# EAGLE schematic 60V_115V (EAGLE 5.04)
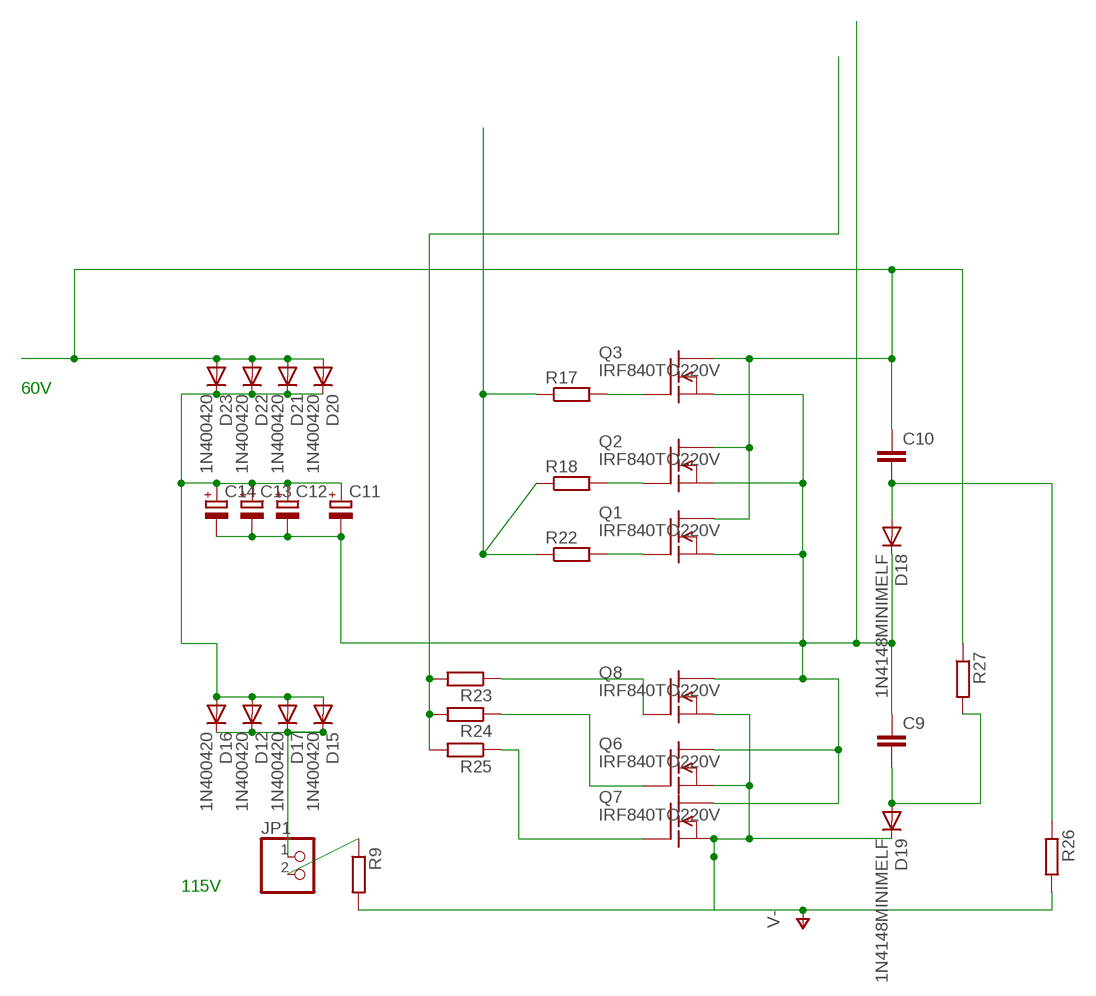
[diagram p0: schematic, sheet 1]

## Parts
C9  C-EUC1812  [C1812]
C10  C-EUC1812K  [C1812K]
C11  CPOL-EUSANYO_SMD_E7  [SANYO-OSCON_SMD_E7]
C12  CPOL-EUSANYO_SMD_E7  [SANYO-OSCON_SMD_E7]
C13  CPOL-EUSANYO_SMD_E7  [SANYO-OSCON_SMD_E7]
C14  CPOL-EUSANYO_SMD_E7  [SANYO-OSCON_SMD_E7]
D12  1N400420  [DO41-20]
D15  1N400420  [DO41-20]
D16  1N400420  [DO41-20]
D17  1N400420  [DO41-20]
D18  1N4148MINIMELF  [MINIMELF]
D19  1N4148MINIMELF  [MINIMELF]
D20  1N400420  [DO41-20]
D21  1N400420  [DO41-20]
D22  1N400420  [DO41-20]
D23  1N400420  [DO41-20]
JP1  PINHD-1X2  [1X02]
Q1  IRF840TO220V  [TO220V]
Q2  IRF840TO220V  [TO220V]
Q3  IRF840TO220V  [TO220V]
Q6  IRF840TO220V  [TO220V]
Q7  IRF840TO220V  [TO220V]
Q8  IRF840TO220V  [TO220V]
R9  R-EU_0207/10  [0207/10]
R17  R-EU_R1206  [R1206]
R18  R-EU_R1206  [R1206]
R22  R-EU_R1206  [R1206]
R23  R-EU_R1206  [R1206]
R24  R-EU_R1206  [R1206]
R25  R-EU_R1206  [R1206]
R26  R-EU_0207/25  [0207/25]
R27  R-EU_0207/30  [0207/30]

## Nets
DRAIN: C9.1 C11.- C12.- C13.- C14.- D18.C Q1.3(S) Q2.3(S) Q3.3(S) Q6.2(D) Q7.2(D) Q8.2(D)
GATE: R17.1 R18.1 R22.1
N$1: JP1.2 R9.1
N$2: C11.+ C12.+ C13.+ C14.+ D12.A D15.A D16.A D17.A D20.C D21.C D22.C D23.C
N$4: Q2.1(G) R18.2
N$9: R23.2 R24.2 R25.2
N$11: Q3.1(G) R17.2
N$23: Q1.1(G) R22.2
N$24: C10.2 D18.A R26.1
N$25: Q7.1(G) R25.1
N$26: Q6.1(G) R24.1
N$27: Q8.1(G) R23.1
N$28: C9.2 D19.A R27.2
OUT+: D12.C D15.C D16.C D17.C JP1.1
V-: D19.C Q6.3(S) Q7.3(S) Q8.3(S) R9.2 R26.2
VIN: C10.1 D20.A D21.A D22.A D23.A Q1.2(D) Q2.2(D) Q3.2(D) R27.1

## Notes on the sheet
- 60V
- 115V

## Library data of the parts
C9 C10 = rcl-2:C-EU: CAPACITOR, European symbol
C11-C14 = rcl-2:CPOL-EU: POLARIZED CAPACITOR, European symbol
D12 D15-D17 D20-D23 = diode-1:1N4004: DIODE
D18 D19 = diode-1:1N4148: DIODE
JP1 = pinhead:PINHD-1X2: PIN HEADER
Q1-Q3 Q6-Q8 = transistor-fet:IRF840: N-Channel Enhancement MOSFET (HEXFET); 500V; 8A; 0,85Ohm
R9 R17 R18 R22-R27 = rcl-2:R-EU_: RESISTOR, European symbol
